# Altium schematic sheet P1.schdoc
size 609 x 533 mm; Symbol: Drawing-Symbol_A4; @Project Name: WYVERN-E; @Page Count: 1; @Update Date: 2026-08-05; @Create Date: 2026-08-05; @Schematic Name: Schematic1; @Page No: 1; @Page Name: P1; Company: EasyEDA.com; Version: V1.0; Page Size: A4; Device: Drawing-Symbol_A4; @Create Time: 14:42:15; @Update Time: 14:42:15; Border: 1; Width: 2400; Height: 2100; Region Start: 1; X Region Count: 6; Y Region Count: 4; Blade Width: 10; Title Block Position: 3; @Board Name: Board1
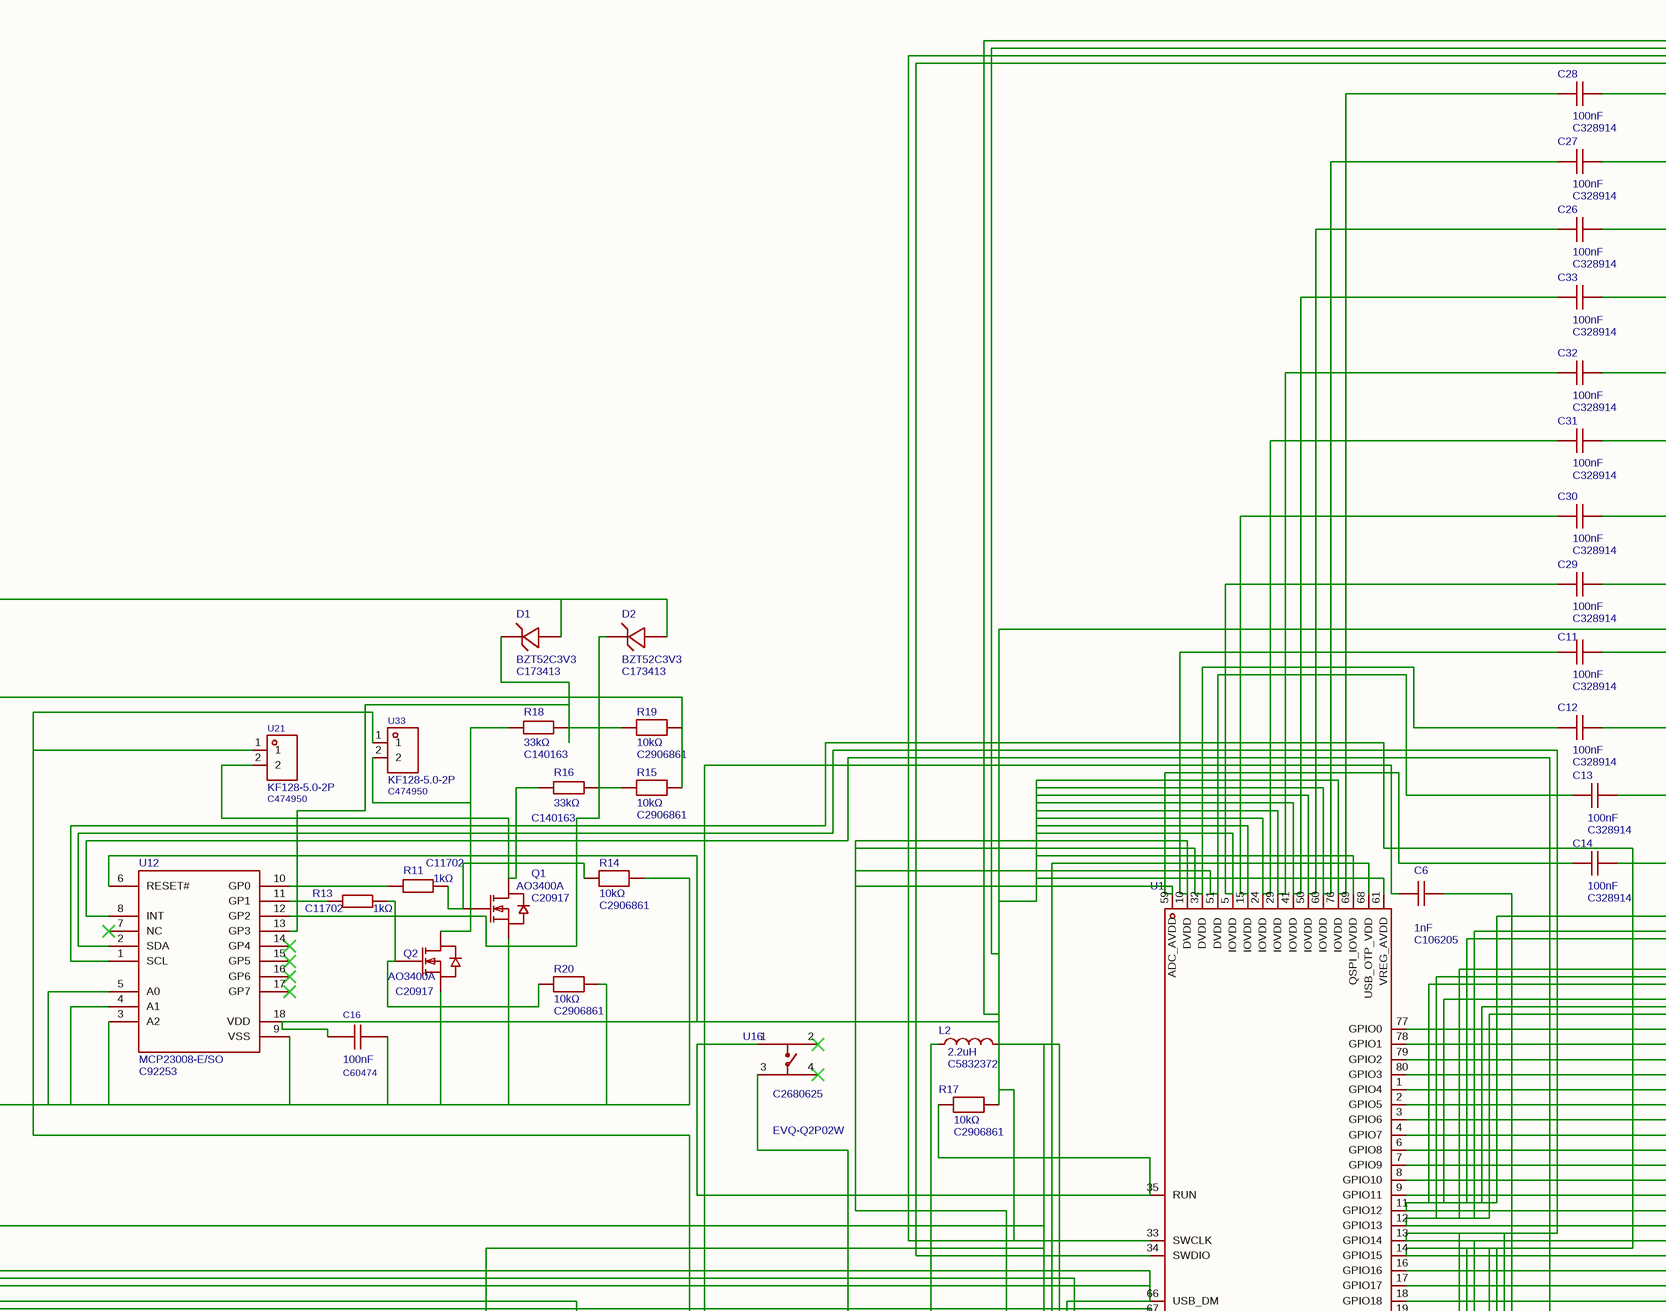
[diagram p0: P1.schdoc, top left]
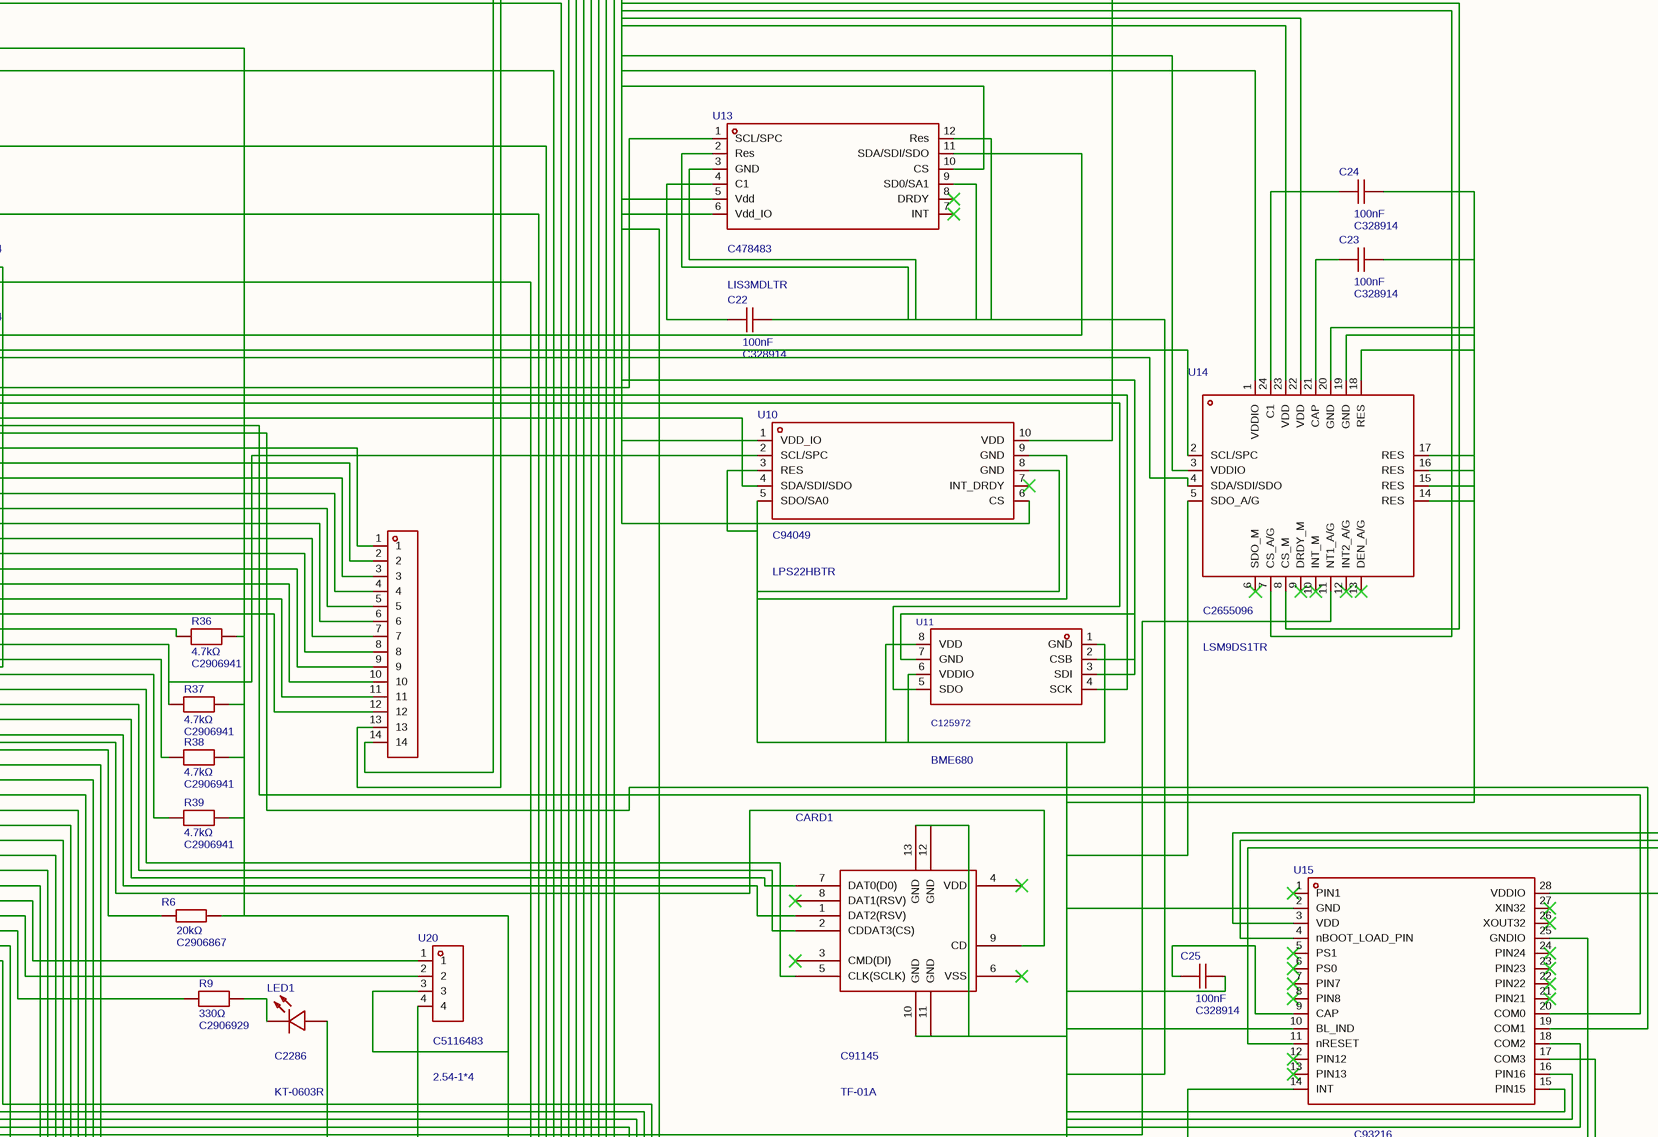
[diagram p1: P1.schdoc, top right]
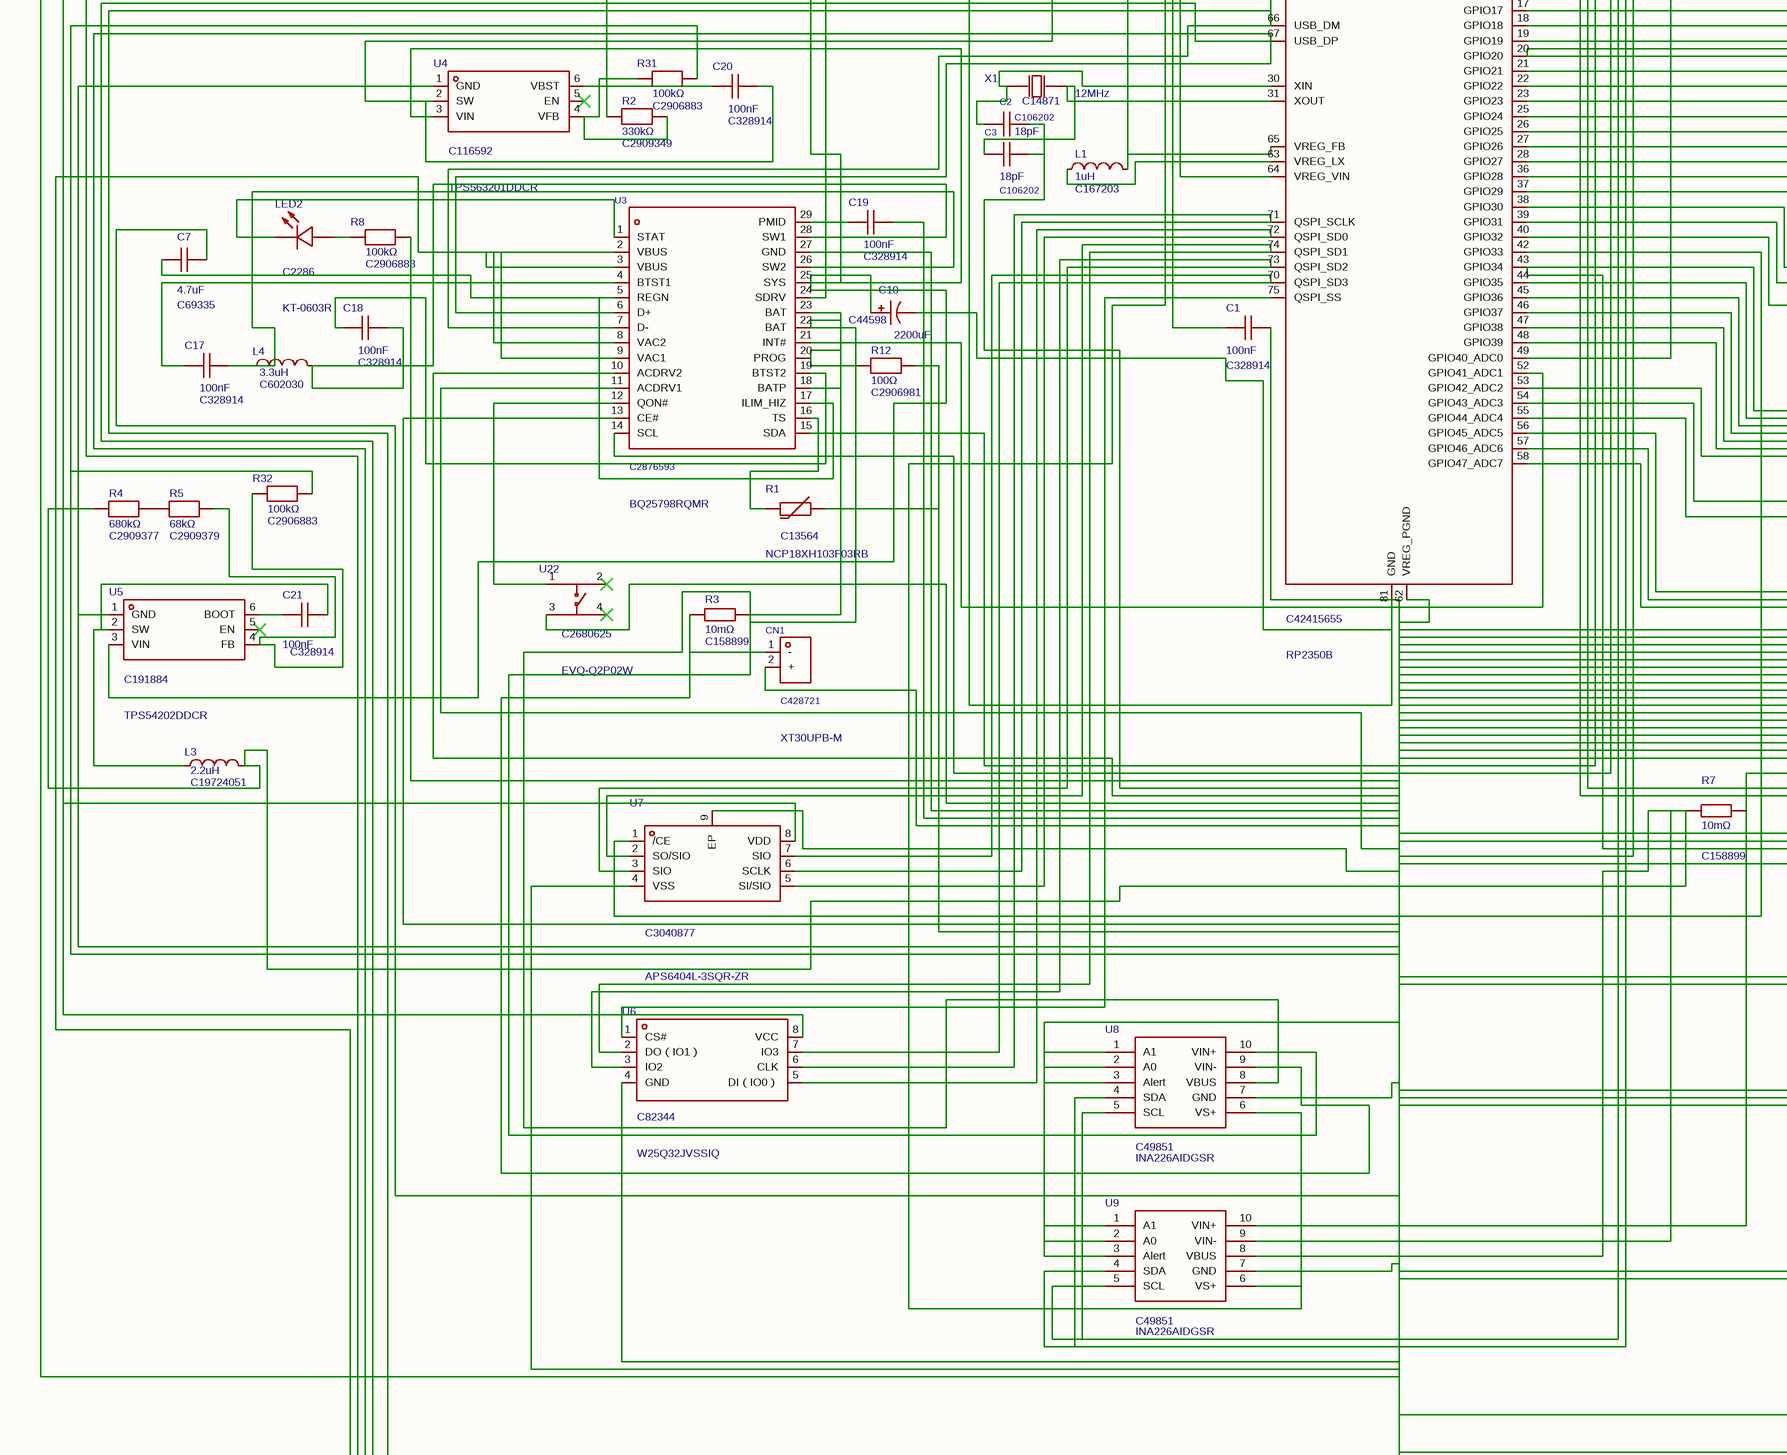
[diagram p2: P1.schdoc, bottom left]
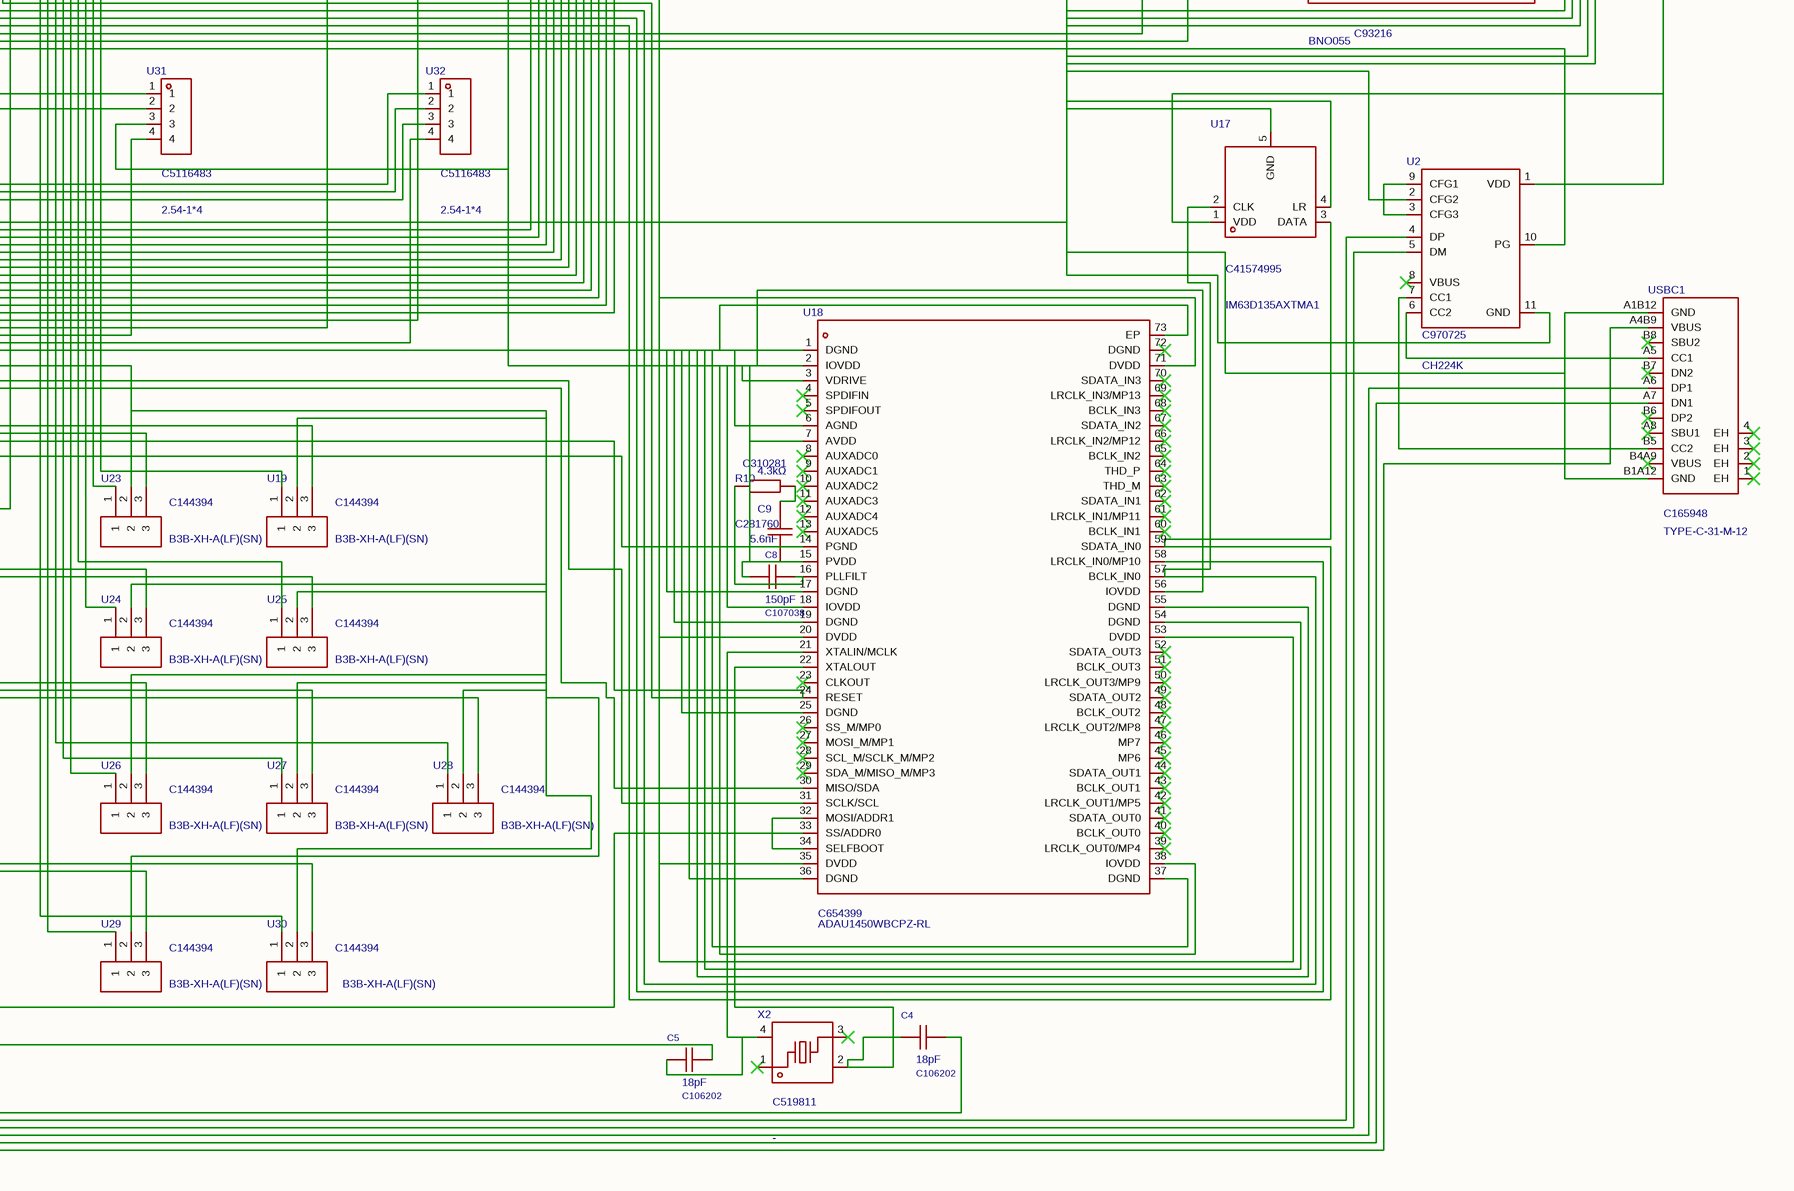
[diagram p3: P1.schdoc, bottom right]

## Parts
C1  100nF  Supplier Part: C328914  [C0402]
C2  18pF  Supplier Part: C106202  [C0402]
C3  18pF  Supplier Part: C106202  [C0402]
C4  18pF  Supplier Part: C106202  [C0402]
C5  18pF  Supplier Part: C106202  [C0402]
C6  1nF  Supplier Part: C106205  [C0402]
C7  4.7uF  Supplier Part: C69335  [C0603]
C8  150pF  Supplier Part: C107038  [C0603]
C9  5.6nF  Supplier Part: C281760  [C0402]
C10  2200uF  Supplier Part: C44598  [CAP-TH_BD13.0-P5.00-D1.2-FD]
C11  100nF  Supplier Part: C328914  [C0402]
C12  100nF  Supplier Part: C328914  [C0402]
C13  100nF  Supplier Part: C328914  [C0402]
C14  100nF  Supplier Part: C328914  [C0402]
C16  100nF  Supplier Part: C60474  [C0402]
C17  100nF  Supplier Part: C328914  [C0402]
C18  100nF  Supplier Part: C328914  [C0402]
C19  100nF  Supplier Part: C328914  [C0402]
C20  100nF  Supplier Part: C328914  [C0402]
C21  100nF  Supplier Part: C328914  [C0402]
C22  100nF  Supplier Part: C328914  [C0402]
C23  100nF  Supplier Part: C328914  [C0402]
C24  100nF  Supplier Part: C328914  [C0402]
C25  100nF  Supplier Part: C328914  [C0402]
C26  100nF  Supplier Part: C328914  [C0402]
C27  100nF  Supplier Part: C328914  [C0402]
C28  100nF  Supplier Part: C328914  [C0402]
C29  100nF  Supplier Part: C328914  [C0402]
C30  100nF  Supplier Part: C328914  [C0402]
C31  100nF  Supplier Part: C328914  [C0402]
C32  100nF  Supplier Part: C328914  [C0402]
C33  100nF  Supplier Part: C328914  [C0402]
CARD1  TF-01A  Supplier Part: C91145  [TF-SMD_TF-01A]
CN1  XT30UPB-M  Supplier Part: C428721  [CONN-TH_XT30UPB-M]
D1  BZT52C3V3  Supplier Part: C173413  [SOD-123_L2.7-W1.6-LS3.7-RD]
D2  BZT52C3V3  Supplier Part: C173413  [SOD-123_L2.7-W1.6-LS3.7-RD]
H1  2011-1X14G00SB  [HDR-TH_14P-P2.54-V-M_4]  (value not drawn)
L1  1uH  Supplier Part: C167203  [IND-SMD_L4.4-W4.2]
L2  2.2uH  Supplier Part: C5832372  [IND-SMD_L2.5-W2.0_MHCHL2520]
L3  2.2uH  Supplier Part: C19724051  [IND-SMD_L5.5-W5.2_NBMC0530N]
L4  3.3uH  Supplier Part: C602030  [IND-SMD_L4.0-W4.0]
LED1  KT-0603R  Supplier Part: C2286  [LED-SMD_L1.6-W0.8-R-RD]
LED2  KT-0603R  Supplier Part: C2286  [LED-SMD_L1.6-W0.8-R-RD]
Q1  AO3400A  Supplier Part: C20917  [SOT-23-3_L2.9-W1.3-P1.90-LS2.4-BR]
Q2  AO3400A  Supplier Part: C20917  [SOT-23-3_L2.9-W1.3-P1.90-LS2.4-BR]
R1  NCP18XH103F03RB  Supplier Part: C13564  [R0603]
R2  330kΩ  Supplier Part: C2909349  [R0402]
R3  10mΩ  Supplier Part: C158899  [R0603]
R4  680kΩ  Supplier Part: C2909377  [R0402]
R5  68kΩ  Supplier Part: C2909379  [R0402]
R6  20kΩ  Supplier Part: C2906867  [R0402]
R7  10mΩ  Supplier Part: C158899  [R0603]
R8  100kΩ  Supplier Part: C2906883  [R0402]
R9  330Ω  Supplier Part: C2906929  [R0402]
R10  4.3kΩ  Supplier Part: C310281  [R0603]
R11  1kΩ  Supplier Part: C11702  [R0402]
R12  100Ω  Supplier Part: C2906981  [R0603]
R13  1kΩ  Supplier Part: C11702  [R0402]
R14  10kΩ  Supplier Part: C2906861  [R0402]
R15  10kΩ  Supplier Part: C2906861  [R0402]
R16  33kΩ  Supplier Part: C140163  [R0402]
R17  10kΩ  Supplier Part: C2906861  [R0402]
R18  33kΩ  Supplier Part: C140163  [R0402]
R19  10kΩ  Supplier Part: C2906861  [R0402]
R20  10kΩ  Supplier Part: C2906861  [R0402]
R31  100kΩ  Supplier Part: C2906883  [R0402]
R32  100kΩ  Supplier Part: C2906883  [R0402]
R36  4.7kΩ  Supplier Part: C2906941  [R0402]
R37  4.7kΩ  Supplier Part: C2906941  [R0402]
R38  4.7kΩ  Supplier Part: C2906941  [R0402]
R39  4.7kΩ  Supplier Part: C2906941  [R0402]
U1  RP2350B  Supplier Part: C42415655  [QFN-80_L10.0-W10.0-P0.40-TL-EP3.4]
U2  CH224K  Supplier Part: C970725  [ESSOP-10_L4.9-W3.9-P1.0-LS6.0-TL-EP]
U3  BQ25798RQMR  Supplier Part: C2876593  [QFN-29_L4.0-W4.0-P0.40-TL-BQ25792RQMR]
U4  TPS563201DDCR  Supplier Part: C116592  [SOT-23-6_L2.9-W1.6-P0.95-LS2.8-BR]
U5  TPS54202DDCR  Supplier Part: C191884  [SOT-23-6_L2.9-W1.6-P0.95-LS2.8-BL]
U6  W25Q32JVSSIQ  Supplier Part: C82344  [SOIC-8_L5.3-W5.3-P1.27-LS8.0-BL]
U7  APS6404L-3SQR-ZR  Supplier Part: C3040877  [USON-8_L3.0-W2.0-P0.50-BL-EP]
U8  INA226AIDGSR  Supplier Part: C49851  [MSOP-10_L3.0-W3.0-P0.50-LS5.0-BL]
U9  INA226AIDGSR  Supplier Part: C49851  [MSOP-10_L3.0-W3.0-P0.50-LS5.0-BL]
U10  LPS22HBTR  Supplier Part: C94049  [HLGA-10L_LPS22HBTR]
U11  BME680  Supplier Part: C125972  [LGA-8_L3.0-W3.0-P0.80-TR]
U12  MCP23008-E/SO  Supplier Part: C92253  [SOIC-18_L11.6-W7.5-P1.27-LS10.3-BL]
U13  LIS3MDLTR  Supplier Part: C478483  [LGA-12_L2.0-W2.0-P0.50-BL]
U14  LSM9DS1TR  Supplier Part: C2655096  [LGA-24_L3.5-W3.0-P0.43-TL]
U15  BNO055  Supplier Part: C93216  [LGA-28_L5.2-W3.8-P0.50-BL]
U16  EVQ-Q2P02W  Supplier Part: C2680625  [SW-SMD_4P-L6.5-W6.0-P4.00-LS6.6-TL]
U17  IM63D135AXTMA1  Supplier Part: C41574995  [MIC-SMD_5P-L3.5-W2.7_IM66D130AXTMA1]
U18  ADAU1450WBCPZ-RL  Supplier Part: C654399  [LFCSP-72_L10.0-W9.8-P0.50-LS10.2-TL-EP5.5]
U19  B3B-XH-A(LF)(SN)  Supplier Part: C144394  [CONN-TH_3P-P2.50_A2501WV2-3P]
U20  2.54-1*4  Supplier Part: C5116483  [HDR-TH_4P-P2.54-V-M-1]
U21  KF128-5.0-2P  Supplier Part: C474950  [CONN-TH_P5.00_KF128-5.0-2P]
U22  EVQ-Q2P02W  Supplier Part: C2680625  [SW-SMD_4P-L6.5-W6.0-P4.00-LS6.6-TL]
U23  B3B-XH-A(LF)(SN)  Supplier Part: C144394  [CONN-TH_3P-P2.50_A2501WV2-3P]
U24  B3B-XH-A(LF)(SN)  Supplier Part: C144394  [CONN-TH_3P-P2.50_A2501WV2-3P]
U25  B3B-XH-A(LF)(SN)  Supplier Part: C144394  [CONN-TH_3P-P2.50_A2501WV2-3P]
U26  B3B-XH-A(LF)(SN)  Supplier Part: C144394  [CONN-TH_3P-P2.50_A2501WV2-3P]
U27  B3B-XH-A(LF)(SN)  Supplier Part: C144394  [CONN-TH_3P-P2.50_A2501WV2-3P]
U28  B3B-XH-A(LF)(SN)  Supplier Part: C144394  [CONN-TH_3P-P2.50_A2501WV2-3P]
U29  B3B-XH-A(LF)(SN)  Supplier Part: C144394  [CONN-TH_3P-P2.50_A2501WV2-3P]
U30  B3B-XH-A(LF)(SN)  Supplier Part: C144394  [CONN-TH_3P-P2.50_A2501WV2-3P]
U31  2.54-1*4  Supplier Part: C5116483  [HDR-TH_4P-P2.54-V-M-1]
U32  2.54-1*4  Supplier Part: C5116483  [HDR-TH_4P-P2.54-V-M-1]
U33  KF128-5.0-2P  Supplier Part: C474950  [CONN-TH_P5.00_KF128-5.0-2P]
USBC1  TYPE-C-31-M-12  Supplier Part: C165948  [USB-C_SMD-TYPE-C-31-M-12_1]
X1  12MHz  Supplier Part: C14871  [HC-49S_L11.4-W4.8]
X2  -  Supplier Part: C519811  [CRYSTAL-SMD_4P-L3.2-W2.5-BL]

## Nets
NetC1_1: C1.1 U1.68(USB_OTP_VDD)
NetC1_2: C1.2 C2.2 C3.2 C4.2 C5.2 C6.2 C7.2 C10.2 C11.2 C12.2 C13.2 C14.2 C16.2 C19.2 C22.2 C23.2 C24.2 C25.2 C26.2 C27.2 C28.2 C29.2 C30.2 C31.2 C32.2 C33.2 CARD1.10(GND) CARD1.11(GND) CARD1.12(GND) CARD1.13(GND) CN1.2(+) D1.2(A) D2.2(A) LED1.1(A) Q1.2(S) Q2.2(S) R1.2 R8.2 R12.2 R14.2 R15.2 R19.2 R20.2 R31.2 R32.2 U1.62(VREG_PGND) U1.81(GND) U2.2(CFG2) U2.3(CFG3) U2.9(CFG1) U2.11(GND) U3.10(ACDRV2) U3.11(ACDRV1) U3.13(CE#) U3.27(GND) U4.1(GND) U5.1(GND) U6.4(GND) U7.4(VSS) U7.9(EP) U8.1(A1) U8.2(A0) U8.3(Alert) U8.7(GND) U9.1(A1) U9.2(A0) U9.3(Alert) U9.7(GND) U10.3(RES) U10.5(SDO/SA0) U10.8(GND) U10.9(GND) U11.1(GND) U11.6(VDDIO) U11.8(VDD) U12.3(A2) U12.4(A1) U12.5(A0) U12.9(VSS) U13.2(Res) U13.3(GND) U13.9(SD0/SA1) U13.12(Res) U14.5(SDO_A/G) U14.14(RES) U14.15(RES) U14.16(RES) U14.17(RES) U14.18(RES) U14.19(GND) U14.20(GND) U15.2(GND) U15.10(BL_IND) U15.15(PIN15) U15.16(PIN16) U15.17(COM3) U15.18(COM2) U15.25(GNDIO) U16.3 U17.4(LR) U17.5(GND) U18.1(DGND) U18.6(AGND) U18.14(PGND) U18.17(DGND) U18.19(DGND) U18.25(DGND) U18.32(MOSI/ADDR1) U18.33(SS/ADDR0) U18.34(SELFBOOT) U18.36(DGND) U18.37(DGND) U18.54(DGND) U18.55(DGND) U18.73(EP) U19.3 U20.4 U22.3 U23.3 U24.3 U25.3 U26.3 U27.3 U28.3 U29.3 U30.3 U31.4 U32.4 USBC1.A1B12(GND) USBC1.B1A12(GND)
NetC2_1: C2.1 U1.30(XIN) X1.2(OSC2)
NetC3_1: C3.1 U1.31(XOUT) X1.1(OSC1)
NetC4_1: C4.1 U18.22(XTALOUT) X2.2(GND)
NetC5_1: C5.1 U18.21(XTALIN/MCLK) X2.4(GND)
NetC6_1: C6.1 U3.24(SDRV)
NetC7_1: C7.1 U3.5(REGN) U3.17(ILIM_HIZ)
NetC8_1: C8.1 C9.1 C16.1 C26.1 C27.1 C28.1 C29.1 C30.1 C31.1 C32.1 C33.1 H1.13 L2.2 R2.1 R6.2 R17.2 R36.2 R37.2 R38.2 R39.2 U1.5(IOVDD) U1.15(IOVDD) U1.24(IOVDD) U1.29(IOVDD) U1.33(SWCLK) U1.41(IOVDD) U1.50(IOVDD) U1.60(IOVDD) U1.61(VREG_AVDD) U1.64(VREG_VIN) U1.69(QSPI_IOVDD) U1.76(IOVDD) U2.1(VDD) U6.8(VCC) U7.8(VDD) U8.6(VS+) U9.6(VS+) U10.1(VDD_IO) U10.6(CS) U10.10(VDD) U11.2(CSB) U11.3(SDI) U11.7(GND) U12.6(RESET#) U12.18(VDD) U13.5(Vdd) U13.6(Vdd_IO) U13.10(CS) U14.1(VDDIO) U14.3(VDDIO) U14.7(CS_A/G) U14.8(CS_M) U14.22(VDD) U14.23(VDD) U15.3(VDD) U15.4(nBOOT_LOAD_PIN) U15.11(nRESET) U15.28(VDDIO) U17.1(VDD) U18.2(IOVDD) U18.3(VDRIVE) U18.7(AVDD) U18.15(PVDD) U18.18(IOVDD) U18.20(DVDD) U18.35(DVDD) U18.38(IOVDD) U18.53(DVDD) U18.56(IOVDD) U18.71(DVDD) U20.3 U31.3
NetC8_2: C8.2 R10.1 U18.16(PLLFILT)
NetC9_2: C9.2 R10.2
NetC10_1: C10.1 U3.25(SYS) U4.3(VIN) U5.3(VIN) U21.1 U33.1
NetC11_1: C11.1 C12.1 C13.1 C14.1 L1.2 U1.10(DVDD) U1.32(DVDD) U1.51(DVDD) U1.59(ADC_AVDD) U1.65(VREG_FB)
NetC17_1: C17.1 U3.4(BTST1)
NetC17_2: C17.2 L4.1 U3.26(SW2)
NetC18_1: C18.1 U3.19(BTST2)
NetC18_2: C18.2 L4.2 U3.28(SW1)
NetC19_1: C19.1 U3.29(PMID)
NetC20_1: C20.1 U4.6(VBST)
NetC20_2: C20.2 L2.1 U4.2(SW)
NetC21_1: C21.1 U5.6(BOOT)
NetC21_2: C21.2 L3.1 U5.2(SW)
NetC22_1: C22.1 U13.4(C1)
NetC23_1: C23.1 U14.21(CAP)
NetC24_1: C24.1 U14.24(C1)
NetC25_1: C25.1 U15.9(CAP)
NetCARD1_1: CARD1.1(DAT2(RSV)) U1.19(GPIO19)
NetCARD1_2: CARD1.2(CDDAT3(CS)) U1.17(GPIO17)
NetCARD1_5: CARD1.5(CLK(SCLK)) U1.16(GPIO16)
NetCARD1_7: CARD1.7(DAT0(D0)) U1.18(GPIO18)
NetCARD1_9: CARD1.9(CD) R6.1 U1.20(GPIO20)
NetCN1_1: CN1.1(-) R3.2 U8.9(VIN-)
NetD1_1: D1.1(K) R18.2 R19.1 U12.13(GP3)
NetD2_1: D2.1(K) R15.1 R16.2 U12.12(GP2)
NetH1_1: H1.1 U1.77(GPIO0)
NetH1_2: H1.2 U1.78(GPIO1)
NetH1_3: H1.3 U1.79(GPIO2)
NetH1_4: H1.4 U1.80(GPIO3)
NetH1_5: H1.5 U1.1(GPIO4)
NetH1_6: H1.6 U1.2(GPIO5)
NetH1_7: H1.7 U1.3(GPIO6)
NetH1_8: H1.8 U1.4(GPIO7)
NetH1_9: H1.9 U1.6(GPIO8)
NetH1_10: H1.10 U1.7(GPIO9)
NetH1_11: H1.11 U1.8(GPIO10)
NetH1_12: H1.12 U1.9(GPIO11)
NetH1_14: H1.14 U1.34(SWDIO)
NetL1_1: L1.1 U1.63(VREG_LX)
NetL3_2: L3.2 R4.1 R7.2 U9.8(VBUS) U9.9(VIN-)
NetLED1_2: LED1.2(K) R9.2
NetLED2_1: LED2.1(A) R8.1
NetLED2_2: LED2.2(K) U3.1(STAT)
NetQ1_1: Q1.1(G) R11.2 R14.1
NetQ1_3: Q1.3(D) R16.1 U21.2
NetQ2_1: Q2.1(G) R13.2 R20.1
NetQ2_3: Q2.3(D) R18.1 U33.2
NetR1_1: R1.1 U3.16(TS)
NetR2_2: R2.2 R31.1 U4.4(VFB)
NetR3_1: R3.1 R12.1 U3.18(BATP) U3.20(PROG) U3.22(BAT) U3.23(BAT) U8.8(VBUS) U8.10(VIN+)
NetR4_2: R4.2 R5.1
NetR5_2: R5.2 R32.1 U5.4(FB)
NetR7_1: R7.1 U9.10(VIN+) U19.2 U23.2 U24.2 U25.2 U26.2 U27.2 U28.2 U29.2 U30.2
NetR9_1: R9.1 U1.40(GPIO32)
NetR11_1: R11.1 U12.10(GP0)
NetR13_1: R13.1 U12.11(GP1)
NetR17_1: R17.1 U1.35(RUN) U16.1
NetR36_1: R36.1 U1.11(GPIO12) U10.4(SDA/SDI/SDO) U11.5(SDO) U13.11(SDA/SDI/SDO) U14.4(SDA/SDI/SDO) U15.20(COM0)
NetR37_1: R37.1 U1.12(GPIO13) U10.2(SCL/SPC) U11.4(SCK) U13.1(SCL/SPC) U14.2(SCL/SPC) U15.19(COM1)
NetR38_1: R38.1 U1.13(GPIO14) U3.15(SDA) U8.4(SDA) U9.4(SDA) U12.2(SDA) U18.30(MISO/SDA)
NetR39_1: R39.1 U1.14(GPIO15) U3.14(SCL) U8.5(SCL) U9.5(SCL) U12.1(SCL) U18.31(SCLK/SCL)
NetU1_21: U1.21(GPIO21) U19.1
NetU1_22: U1.22(GPIO22) U23.1
NetU1_23: U1.23(GPIO23) U24.1
NetU1_25: U1.25(GPIO24) U25.1
NetU1_26: U1.26(GPIO25) U26.1
NetU1_27: U1.27(GPIO26) U27.1
NetU1_28: U1.28(GPIO27) U28.1
NetU1_36: U1.36(GPIO28) U29.1
NetU1_37: U1.37(GPIO29) U30.1
NetU1_38: U1.38(GPIO30) U20.1
NetU1_39: U1.39(GPIO31) U20.2
NetU1_42: U1.42(GPIO33) U7.1(/CE)
NetU1_43: U1.43(GPIO34) U18.24(RESET)
NetU1_44: U1.44(GPIO35) U17.2(CLK) U18.57(BCLK_IN0)
NetU1_45: U1.45(GPIO36) U18.58(LRCLK_IN0/MP10)
NetU1_46: U1.46(GPIO37) U17.3(DATA) U18.59(SDATA_IN0)
NetU1_47: U1.47(GPIO38) U14.11(NT1_A/G)
NetU1_48: U1.48(GPIO39) U15.14(INT)
NetU1_49: U1.49(GPIO40_ADC0) U12.8(INT)
NetU1_52: U1.52(GPIO41_ADC1) U3.21(INT#)
NetU1_53: U1.53(GPIO42_ADC2) U2.10(PG)
NetU1_54: U1.54(GPIO43_ADC3) U31.1
NetU1_55: U1.55(GPIO44_ADC4) U31.2
NetU1_56: U1.56(GPIO45_ADC5) U32.1
NetU1_57: U1.57(GPIO46_ADC6) U32.2
NetU1_58: U1.58(GPIO47_ADC7) U32.3
NetU1_66: U1.66(USB_DM) U2.4(DP) U3.7(D-) USBC1.A7(DN1)
NetU1_67: U1.67(USB_DP) U2.5(DM) U3.6(D+) USBC1.A6(DP1)
NetU1_70: U1.70(QSPI_SD3) U6.7(IO3) U7.7(SIO)
NetU1_71: U1.71(QSPI_SCLK) U6.6(CLK) U7.6(SCLK)
NetU1_72: U1.72(QSPI_SD0) U6.5(DI（IO0）) U7.5(SI/SIO)
NetU1_73: U1.73(QSPI_SD2) U6.3(IO2) U7.3(SIO)
NetU1_74: U1.74(QSPI_SD1) U6.2(DO（IO1）) U7.2(SO/SIO)
NetU1_75: U1.75(QSPI_SS) U6.1(CS#)
NetU2_6: U2.6(CC2) USBC1.A5(CC1)
NetU2_7: U2.7(CC1) USBC1.B5(CC2)
NetU3_2: U3.2(VBUS) U3.3(VBUS) U3.8(VAC2) U3.9(VAC1) USBC1.A4B9(VBUS)
NetU3_12: U3.12(QON#) U22.1

Not connected (* = marked no-connect by the designer): CARD1 3(CMD(DI))* 4(VDD)* 6(VSS)* 8(DAT1(RSV))*; U2 8(VBUS)*; U4 5(EN)*; U5 5(EN)*; U10 7(INT_DRDY)*; U12 7(NC)* 14(GP4)* 15(GP5)* 16(GP6)* 17(GP7)*; U13 7(INT)* 8(DRDY)*; U14 6(SDO_M)* 9(DRDY_M)* 10(INT_M)* 12(INT2_A/G)* 13(DEN_A/G)*; U15 1(PIN1)* 5(PS1)* 6(PS0)* 7(PIN7)* 8(PIN8)* 12(PIN12)* 13(PIN13)* 21(PIN21)* 22(PIN22)* 23(PIN23)* 24(PIN24)* 26(XOUT32)* 27(XIN32)*; U16 2* 4*; U18 4(SPDIFIN)* 5(SPDIFOUT)* 8(AUXADC0)* 9(AUXADC1)* 10(AUXADC2)* 11(AUXADC3)* 12(AUXADC4)* 13(AUXADC5)* 23(CLKOUT)* 26(SS_M/MP0)* 27(MOSI_M/MP1)* 28(SCL_M/SCLK_M/MP2)* 29(SDA_M/MISO_M/MP3)* 39(LRCLK_OUT0/MP4)* 40(BCLK_OUT0)* 41(SDATA_OUT0)* 42(LRCLK_OUT1/MP5)* 43(BCLK_OUT1)* 44(SDATA_OUT1)* 45(MP6)* 46(MP7)* 47(LRCLK_OUT2/MP8)* 48(BCLK_OUT2)* 49(SDATA_OUT2)* 50(LRCLK_OUT3/MP9)* 51(BCLK_OUT3)* 52(SDATA_OUT3)* 60(BCLK_IN1)* 61(LRCLK_IN1/MP11)* 62(SDATA_IN1)* 63(THD_M)* 64(THD_P)* 65(BCLK_IN2)* 66(LRCLK_IN2/MP12)* 67(SDATA_IN2)* 68(BCLK_IN3)* 69(LRCLK_IN3/MP13)* 70(SDATA_IN3)* 72(DGND)*; U22 2* 4*; USBC1 1(EH)* 2(EH)* 3(EH)* 4(EH)* A8(SBU1)* B4A9(VBUS)* B6(DP2)* B7(DN2)* B8(SBU2)*; X2 1* 3*

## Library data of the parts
C1 C11-C14 C17-C33 = FN15X104K160PNG: Capacitance:100nF Tolerance:±10% Tolerance:±10% Voltage Rating:16V Temperature Coefficient:X7R; Manufacturer: PSA(信昌电陶); AddInBom: yes; ModelId: b7d13df3e9464d7a99d0651d1a5b4d570819f05c4eef4c71ace90d822a990e87; ModelName: C0402_L1.0-W0.5-H0.5; ModelTransform: 39.37,19.685,0,0,0,0,0,0,0; Tolerance: ±10%; Voltage Rating: 16V; Temperature Coefficient: X7R
C2-C5 = CC0402JRNPO9BN180: Capacitance:18pF Tolerance:±5% Tolerance:±5% Voltage Rating:50V Temperature Coefficient:NP0; Manufacturer: YAGEO(国巨); AddInBom: yes; ModelId: b7d13df3e9464d7a99d0651d1a5b4d570819f05c4eef4c71ace90d822a990e87; ModelName: C0402_L1.0-W0.5-H0.5; ModelTransform: 39.37,19.685,0,0,0,0,0,0,0; Tolerance: ±5%; Voltage Rating: 50V; Temperature Coefficient: NP0
C6 = CC0402KRX7R9BB102: Capacitance: Tolerance:±10% Tolerance:±10% Voltage Rated: Temperature Coefficient:; Manufacturer: YAGEO(国巨); AddInBom: yes; ModelId: b7d13df3e9464d7a99d0651d1a5b4d570819f05c4eef4c71ace90d822a990e87; ModelName: C0402_L1.0-W0.5-H0.5; ModelTransform: 39.37,19.685,0,0,0,0,0,0,0; Tolerance: ±10%
C7 = CL10A475KA8NQNC: Capacitance:4.7uF Tolerance:±10% Tolerance:±10% Voltage Rating:25V Temperature Coefficient:X5R; Manufacturer: SAMSUNG(三星); AddInBom: yes; ModelId: 624118aa3cc7497086c383c2d72e08520819f05c4eef4c71ace90d822a990e87; ModelName: C0603_L1.6-W0.8-H0.8; ModelTransform: 62.992,31.496,0,0,0,0,0,0,0; Tolerance: ±10%; Voltage Rating: 25V; Temperature Coefficient: X5R
C8 = CC0603JRNPO9BN151: Capacitance:150pF Tolerance:±5% Tolerance:±5% Voltage Rating:50V Temperature Coefficient:NP0; Manufacturer: YAGEO(国巨); AddInBom: yes; ModelId: 624118aa3cc7497086c383c2d72e08520819f05c4eef4c71ace90d822a990e87; ModelName: C0603_L1.6-W0.8-H0.8; ModelTransform: 62.992,31.496,0,0,0,0,0,0,0; Tolerance: ±5%; Voltage Rating: 50V; Temperature Coefficient: NP0
C9 = CC0402KRX7R9BB562: Capacitance:5.6nF Tolerance:±10% Tolerance:±10% Voltage Rating:50V Temperature Coefficient:X7R; Manufacturer: YAGEO(国巨); AddInBom: yes; ModelId: b7d13df3e9464d7a99d0651d1a5b4d570819f05c4eef4c71ace90d822a990e87; ModelName: C0402_L1.0-W0.5-H0.5; ModelTransform: 39.37,19.685,0,0,0,0,0,0,0; Tolerance: ±10%; Voltage Rating: 50V; Temperature Coefficient: X7R
C10 = KM228M025J20RR0VH2FP0: Capacitance:2200uF Tolerance:±20% Tolerance:±20% Voltage Rating:25V Ripple Current:- Equivalent Series Resistance(ESR):- Pin Spacing:5mm Diameter:13mm Height - Seated (Max):20mm Lifetime:2000hrs@105℃; Manufacturer: Chengx(承兴); Symbol: 2200uF 25V 13*20; AddInBom: yes; ModelId: 7c9983bf978a4fc5a02c9caad056438d0819f05c4eef4c71ace90d822a990e87; ModelTransform: 492.5187,492.025,0,0,0,0,0,0,-137.795; Tolerance: ±20%; Voltage Rating: 25V; Pin Spacing: 5mm
C16 = CC0402KRX7R7BB104: Capacitance:100nF Tolerance:±10% Tolerance:±10% Voltage Rating:16V Temperature Coefficient:X7R; Manufacturer: YAGEO(国巨); AddInBom: yes; ModelId: b7d13df3e9464d7a99d0651d1a5b4d570819f05c4eef4c71ace90d822a990e87; ModelName: C0402_L1.0-W0.5-H0.5; ModelTransform: 39.37,19.685,0,0,0,0,0,0,0; Tolerance: ±10%; Voltage Rating: 16V; Temperature Coefficient: X7R
CARD1 = TF-01A_C91145: Card Connection Mode:Push-Push Card Type:MicroSD Card (TF Card) Connector Type:Connector and Ejector Additional Card Detection Pins:- Supplementary Features:With Locating Pins Height Above Board:1.85mm Operating Temperature:- Operating Temperature:-; Manufacturer: 韩国韩荣; Add into BOM: yes; ModelId: 5685a23adc9a4e3e9b914abe5ae03aae0819f05c4eef4c71ace90d822a990e87; ModelTransform: 633.85696,590.65303,0,0,0,0,0,-85.63,-23.622
CN1 = XT30UPB-M: Rated current:15A Rated voltage: colour:Yellow Connector type:Model aircraft plug contact resistance: interface form:Male insulating material: metal material:Gold plating; Manufacturer: AMASS(艾迈斯); Add into BOM: yes; ModelId: 8606296c6a2a4a0aa30f28b26a2c1e3a0819f05c4eef4c71ace90d822a990e87; ModelTransform: 401.574,204.724,0,0,0,0,0,0,-78.74; Rated current: 15A; interface form: Male
D1 D2 = BZT52C3V3_C173413: Diode Configuration:1 Independent Zener Voltage(Nom):3.3V Reverse Leakage Current (Ir):20uA@1V Zener Voltage(Range):3.14V~3.47V Zener Voltage(Range):3.14V~3.47V Pd - Power Dissipation:500mW Impedance(Zzt):130Ω Impedance(Zzk):- Operating Junction Temperatu; Manufacturer: MDD(辰达半导体); AddInBom: yes; ModelId: 31ae3d5c025440ebafdeabfabec0ebeb0819f05c4eef4c71ace90d822a990e87; ModelName: SOD-123_L2.7-W1.6-H1.4-LS3.7; ModelTransform: 146.026,62.992,0,180,0,0,0.0005,0,0; Zener Voltage(Nom): 3.3V; Pd - Power Dissipation: 500mW; Impedance(Zzt): 130Ω; Tolerance: ±5%
H1 = 2011-1X14G00SB: Pin Structure:1x14P Pitch:2.54mm Circluar Pins/Square Pins:Pin Header Mounting Type:Through Hole Number of Rows:1 Number of Pins:14P Current Rating:3A Voltage Rating (Max):600V Length of Mating Pin:6mm Insulation Height:2.5mm Length of End Connection Pin:; Manufacturer: WingTAT(格林柏); AddInBom: yes; ModelId: f6b8b1151f3d4858b245f95bf957bfbf0819f05c4eef4c71ace90d822a990e87; ModelTransform: 1399.997,98.8187,0,0,0,0,0,0,-118.11; Pin Structure: 1x14P; Pitch: 2.54mm; Current Rating: 3A; Voltage Rating (Max): 600V
L1 = FXL0420-1R0-M: Inductance:1uH Tolerance:±20% Tolerance:±20% Current Rating:6A Current - Saturation(Isat):7A DC Resistance(DCR):27mΩ Type:Molded Inductor; Manufacturer: cjiang(长江微电); AddInBom: yes; ModelId: 202f222253c645ab9b4a671ae12ae5590819f05c4eef4c71ace90d822a990e87; ModelName: IND-SMD_L4.2-W4.4-H2.0; ModelTransform: 173.228,165.354,0,0,0,0,0,0,0; Tolerance: ±20%; Current Rating: 6A; Current - Saturation(Isat): 7A; DC Resistance(DCR): 27mΩ
L2 = FTC252012S2R2MBCA: Inductance:2.2uH Tolerance:±20% Tolerance:±20% Current Rating:3A Current - Saturation(Isat):3.8A DC Resistance(DCR):55mΩ Type:-; Manufacturer: cjiang(长江微电); AddInBom: yes; ModelId: 6030ee72033e42b3943c7a42b03bf5750819f05c4eef4c71ace90d822a990e87; ModelTransform: 98.425,78.74,0,0,0,0,0,0,0; Tolerance: ±20%; Current Rating: 3A; Current - Saturation(Isat): 3.8A; DC Resistance(DCR): 55mΩ
L3 = CY0530AT125DS-2R2MCY: Inductance:2.2uH Tolerance:±20% Tolerance:±20% Current Rating:6A Current - Saturation(Isat):6.7A DC Resistance(DCR):17.3mΩ Type:- Ratings:-; Manufacturer: Sumida(胜美达); AddInBom: yes; Tolerance: ±20%; Current Rating: 6A; Current - Saturation(Isat): 6.7A; DC Resistance(DCR): 17.3mΩ
L4 = FHD4020S-3R3MT: Inductance:3.3uH Tolerance:±20% Tolerance:±20% Current Rating:4A Current - Saturation(Isat):5.9A DC Resistance(DCR):73mΩ Type:Winding Inductor; Manufacturer: cjiang(长江微电); AddInBom: yes; ModelId: eb765a5a931c40af9a8ef05b08821f350819f05c4eef4c71ace90d822a990e87; ModelName: IND-SMD_L4.0-W4.0-H1.9; ModelTransform: 157.48,157.484,0,0,0,0,0,0,0; Tolerance: ±20%; Current Rating: 4A; Current - Saturation(Isat): 5.9A; DC Resistance(DCR): 73mΩ
LED1 LED2 = KT-0603R: Lamp Holder Type:1.6mm x 0.8mm square LED Illumination Color:Red Voltage - Forward(Vf):1.8V~2.4V Voltage - Forward(Vf):1.8V~2.4V Power(Watts):40mW Forward Current:20mA Wavelength - Dominant:615nm~630nm Wavelength - Dominant:615nm~630nm Peak Wavelength:645; Manufacturer: KENTO; Add into BOM: yes; ModelId: 19cc79473bbc420a8203ad67d1a57d420819f05c4eef4c71ace90d822a990e87; ModelName: LED0603_L1.6-W0.8-H0.6; ModelTransform: 63.7794,31.496,0,0,0,0,0,0,0; Illumination Color: Red; Power(Watts): 40mW; Forward Current: 20mA; Peak Wavelength: 645nm; Diode Configuration: Discrete Diode; Lens Color: Water Clear; Luminous Intensity: 300mcd; Viewing Angle: 120°
Q1 Q2 = AO3400A_C20917: Number:- Drain to Source Voltage:30V Current - Continuous Drain(Id):- RDS(on):48mΩ@2.5V Pd - Power Dissipation:- Gate Threshold Voltage (Vgs(th)):1.45V@250uA Gate Charge(Qg):7nC@10V Input Capacitance(Ciss):630pF@15V Reverse Transfer Capacitance (Crss@Vds); Manufacturer: AOS; AddInBom: yes; ModelId: 62a57c6760504a01965db6419a6d07df0819f05c4eef4c71ace90d822a990e87; ModelName: SOT-23-3P_L2.9-W1.3-H1.0-LS2.4-P0.95; ModelTransform: 98.425,114.173,0,180,0,0,0.0005,-0.0005,0; Drain to Source Voltage: 30V; Type: N-Channel
R1 = NCP18XH103F03RB: Power(Watts):100mW Resistance @ 25℃:10kΩ Resistance Tolerance:±1% Resistance Tolerance:±1% B Constant Tolerance:±1% B Constant (25℃/50℃):3380K B Constant (25℃/75℃):- B Constant (25℃/85℃):3434K B Constant (25℃/100℃):3455K Steady State Current (Max):310uA D; Manufacturer: muRata(村田); Add into BOM: yes; ModelId: 112863783b5b41f1b5254f87eedc79320819f05c4eef4c71ace90d822a990e87; ModelTransform: 31.8897,63.7794,0,90,0,0,0,0,0; Power(Watts): 100mW; Resistance @ 25℃: 10kΩ; Resistance Tolerance: ±1%; B Constant (25℃/50℃): 3380K; B Constant (25℃/85℃): 3434K; B Constant (25℃/100℃): 3455K; Steady State Current (Max): 310uA; Dissipation Factor: 1mW/℃
R2 = FRC0402F3303TS: Type:Thick Film Resistor Resistance:330kΩ Tolerance:±1% Tolerance:±1% Power(Watts):62.5mW Voltage-Supply(Max):50V Temperature Coefficient:±100ppm/℃ Temperature Coefficient:±100ppm/℃ Operating Temperature:-55℃~+155℃ Operating Temperature:-55℃~+155℃; Manufacturer: FOJAN(富捷); AddInBom: yes; ModelId: efdecb7dae4442949d28eecaf748420f0819f05c4eef4c71ace90d822a990e87; ModelName: R0402_L1.0-W0.5-H0.4; ModelTransform: 39.37,19.685,0,0,0,0,0,0,0; Tolerance: ±1%; Power(Watts): 62.5mW; Voltage-Supply(Max): 50V
R3 R7 = RTT03R010FTP: Type:Thick Film Resistor Resistance:10mΩ Tolerance:±1% Tolerance:±1% Power(Watts):100mW Temperature Coefficient:±1500ppm/℃ Temperature Coefficient:±1500ppm/℃ Operating Temperature:-55℃~+155℃ Operating Temperature:-55℃~+155℃; Manufacturer: RALEC(旺诠); 3D Model: 112863783b5b41f1b5254f87eedc79320819f05c4eef4c71ace90d822a990e87; 3D Model Transform: 31.8897,63.7794,0,90,0,0,0,0,0; Tolerance: ±1%; Power(Watts): 100mW; AddInBom: yes
R4 = FRC0402F6803TS: Type:Thick Film Resistor Resistance:680kΩ Tolerance:±1% Tolerance:±1% Power(Watts):62.5mW Voltage-Supply(Max):50V Temperature Coefficient:±100ppm/℃ Temperature Coefficient:±100ppm/℃ Operating Temperature:-55℃~+155℃ Operating Temperature:-55℃~+155℃; Manufacturer: FOJAN(富捷); AddInBom: yes; ModelId: efdecb7dae4442949d28eecaf748420f0819f05c4eef4c71ace90d822a990e87; ModelName: R0402_L1.0-W0.5-H0.4; ModelTransform: 39.37,19.685,0,0,0,0,0,0,0; Tolerance: ±1%; Power(Watts): 62.5mW; Voltage-Supply(Max): 50V
R5 = FRC0402F6802TS: Type:Thick Film Resistor Resistance:68kΩ Tolerance:±1% Tolerance:±1% Power(Watts):62.5mW Voltage-Supply(Max):50V Temperature Coefficient:±100ppm/℃ Temperature Coefficient:±100ppm/℃ Operating Temperature:-55℃~+155℃ Operating Temperature:-55℃~+155℃; Manufacturer: FOJAN(富捷); AddInBom: yes; ModelId: efdecb7dae4442949d28eecaf748420f0819f05c4eef4c71ace90d822a990e87; ModelName: R0402_L1.0-W0.5-H0.4; ModelTransform: 39.37,19.685,0,0,0,0,0,0,0; Tolerance: ±1%; Power(Watts): 62.5mW; Voltage-Supply(Max): 50V
R6 = FRC0402F2002TS: Type:Thick Film Resistor Resistance:20kΩ Tolerance:±1% Tolerance:±1% Power(Watts):62.5mW Voltage-Supply(Max):50V Temperature Coefficient:±100ppm/℃ Temperature Coefficient:±100ppm/℃ Operating Temperature:-55℃~+155℃ Operating Temperature:-55℃~+155℃; Manufacturer: FOJAN(富捷); AddInBom: yes; ModelId: efdecb7dae4442949d28eecaf748420f0819f05c4eef4c71ace90d822a990e87; ModelName: R0402_L1.0-W0.5-H0.4; ModelTransform: 39.37,19.685,0,0,0,0,0,0,0; Tolerance: ±1%; Power(Watts): 62.5mW; Voltage-Supply(Max): 50V
R8 R31 R32 = FRC0402J104 TS: Type:Thick Film Resistor Resistance:100kΩ Tolerance:±5% Tolerance:±5% Power(Watts):62.5mW Voltage-Supply(Max):50V Temperature Coefficient:±100ppm/℃ Temperature Coefficient:±100ppm/℃ Operating Temperature:-55℃~+155℃ Operating Temperature:-55℃~+155℃; Manufacturer: FOJAN(富捷); AddInBom: yes; ModelId: efdecb7dae4442949d28eecaf748420f0819f05c4eef4c71ace90d822a990e87; ModelName: R0402_L1.0-W0.5-H0.4; ModelTransform: 39.37,19.685,0,0,0,0,0,0,0; Tolerance: ±5%; Power(Watts): 62.5mW; Voltage-Supply(Max): 50V
R9 = FRC0402J331 TS: Type:Thick Film Resistor Resistance:330Ω Tolerance:±5% Tolerance:±5% Power(Watts):62.5mW Voltage-Supply(Max):50V Temperature Coefficient:±100ppm/℃ Temperature Coefficient:±100ppm/℃ Operating Temperature:-55℃~+155℃ Operating Temperature:-55℃~+155℃; Manufacturer: FOJAN(富捷); AddInBom: yes; ModelId: efdecb7dae4442949d28eecaf748420f0819f05c4eef4c71ace90d822a990e87; ModelName: R0402_L1.0-W0.5-H0.4; ModelTransform: 39.37,19.685,0,0,0,0,0,0,0; Tolerance: ±5%; Power(Watts): 62.5mW; Voltage-Supply(Max): 50V
R10 = RS-03K4301FT: Type:Thick Film Resistors Resistance:4.3kΩ Tolerance:±1% Tolerance:±1% Power(Watts): Overload Voltage (Max): Temperature Coefficient:±100ppm/℃ Temperature Coefficient:±100ppm/℃ Operating Temperature Range:-55℃~+155℃ Operating Temperature Range:-55℃~+155℃; Manufacturer: FH(风华); AddInBom: yes; ModelId: 112863783b5b41f1b5254f87eedc79320819f05c4eef4c71ace90d822a990e87; ModelTransform: 31.8897,63.7794,0,90,0,0,0,0,0; Tolerance: ±1%
R11 R13 = 0402WGF1001TCE: Type:Thick Film Resistor Resistance:1kΩ Tolerance:±1% Tolerance:±1% Power(Watts):62.5mW Voltage-Supply(Max):50V Temperature Coefficient:±100ppm/℃ Temperature Coefficient:±100ppm/℃ Operating Temperature:-55℃~+155℃ Operating Temperature:-55℃~+155℃; Manufacturer: UNI-ROYAL(厚声); AddInBom: yes; ModelId: efdecb7dae4442949d28eecaf748420f0819f05c4eef4c71ace90d822a990e87; ModelName: R0402_L1.0-W0.5-H0.4; ModelTransform: 39.37,19.685,0,0,0,0,0,0,0; Tolerance: ±1%; Power(Watts): 62.5mW; Voltage-Supply(Max): 50V
R12 = FRC0603F1000TS: Type:Thick Film Resistor Resistance:100Ω Tolerance:±1% Tolerance:±1% Power(Watts):100mW Voltage-Supply(Max):75V Temperature Coefficient:±100ppm/℃ Temperature Coefficient:±100ppm/℃ Operating Temperature:-55℃~+155℃ Operating Temperature:-55℃~+155℃; Manufacturer: FOJAN(富捷); AddInBom: yes; ModelId: 112863783b5b41f1b5254f87eedc79320819f05c4eef4c71ace90d822a990e87; ModelTransform: 31.8897,63.7794,0,90,0,0,0,0,0; Tolerance: ±1%; Power(Watts): 100mW; Voltage-Supply(Max): 75V
R14 R15 R19 R20 = FRC0402F1002TS: Type:Thick Film Resistor Resistance:10kΩ Tolerance:±1% Tolerance:±1% Power(Watts):62.5mW Voltage-Supply(Max):50V Temperature Coefficient:±100ppm/℃ Temperature Coefficient:±100ppm/℃ Operating Temperature:-55℃~+155℃ Operating Temperature:-55℃~+155℃; Manufacturer: FOJAN(富捷); 3D Model: efdecb7dae4442949d28eecaf748420f0819f05c4eef4c71ace90d822a990e87; 3D Model Transform: 39.37,19.685,0,0,0,0,0,0,0; Tolerance: ±1%; Power(Watts): 62.5mW; Voltage-Supply(Max): 50V; AddInBom: yes; ModelName: R0402_L1.0-W0.5-H0.4
R16 R18 = RC-02K3302FT: Type:Thick Film Resistor Resistance:33kΩ Tolerance:±1% Tolerance:±1% Power(Watts):62.5mW Voltage-Supply(Max):50V Temperature Coefficient:±100ppm/℃ Temperature Coefficient:±100ppm/℃ Operating Temperature:-55℃~+155℃ Operating Temperature:-55℃~+155℃; Manufacturer: FH(风华); AddInBom: yes; ModelId: efdecb7dae4442949d28eecaf748420f0819f05c4eef4c71ace90d822a990e87; ModelName: R0402_L1.0-W0.5-H0.4; ModelTransform: 39.37,19.685,0,0,0,0,0,0,0; Tolerance: ±1%; Power(Watts): 62.5mW; Voltage-Supply(Max): 50V
R17 = FRC0402F1002TS: Type:Thick Film Resistor Resistance:10kΩ Tolerance:±1% Tolerance:±1% Power(Watts):62.5mW Voltage-Supply(Max):50V Temperature Coefficient:±100ppm/℃ Temperature Coefficient:±100ppm/℃ Operating Temperature:-55℃~+155℃ Operating Temperature:-55℃~+155℃; Manufacturer: FOJAN(富捷); AddInBom: yes; ModelId: efdecb7dae4442949d28eecaf748420f0819f05c4eef4c71ace90d822a990e87; ModelName: R0402_L1.0-W0.5-H0.4; ModelTransform: 39.37,19.685,0,0,0,0,0,0,0; Tolerance: ±1%; Power(Watts): 62.5mW; Voltage-Supply(Max): 50V
R36-R39 = FRC0402J472 TS: Type:Thick Film Resistor Resistance:4.7kΩ Tolerance:±5% Tolerance:±5% Power(Watts):62.5mW Voltage-Supply(Max):50V Temperature Coefficient:±100ppm/℃ Temperature Coefficient:±100ppm/℃ Operating Temperature:-55℃~+155℃ Operating Temperature:-55℃~+155℃; Manufacturer: FOJAN(富捷); AddInBom: yes; ModelId: efdecb7dae4442949d28eecaf748420f0819f05c4eef4c71ace90d822a990e87; ModelName: R0402_L1.0-W0.5-H0.4; ModelTransform: 39.37,19.685,0,0,0,0,0,0,0; Tolerance: ±5%; Power(Watts): 62.5mW; Voltage-Supply(Max): 50V
U1 = RP2350B_C42415655: Number of I/O:48 Features:Independent watchdog (IWDG)；Power-on reset (POR)；True random number generator (TRNG)；Watchdog reset；Built-in general-purpose timer；Hardware ECC check；External pin reset (NRST)；Integrated LDO; Manufacturer: Raspberry Pi(树莓派); Add into BOM: yes; ModelId: 9f007f8a42644ad5aa4c6524189812eb0819f05c4eef4c71ace90d822a990e87; ModelTransform: 394.487,394.487,0,0,0,0,0,0,0; Number of I/O: 48
U2 = CH224K: Type:Power Receiver Controller Protocol:PD 3.0 Number of Channels:- Output Power:100W Output Voltage:5V；20V；15V；12V；9V Voltage - Supply:4V~30V Voltage - Supply:4V~30V Operating Temperature:-40℃~+90℃ Operating Temperature:-40℃~+90℃ Features:Thermal Protect; Manufacturer: WCH(南京沁恒); Add into BOM: yes; ModelId: caddd54494d446ce85a816aa480d5ff10819f05c4eef4c71ace90d822a990e87; ModelTransform: 192.913,236.22,0,0,0,0,0,0,0; Protocol: PD 3.0; Output Power: 100W; Voltage - Supply: 4V~30V
U3 = BQ25798RQMR: The Chip Type:Charging IC Voltage - Supply:3.6V~24V Voltage - Supply:3.6V~24V Charge Current - Max:5A Type of Battery:Lithium Battery Number of Cells:1~4 Number of Cells:1~4 Operating Temperature:-40℃~+85℃ Operating Temperature:-40℃~+85℃ Battery Temperatu; Manufacturer: TI(德州仪器); Add into BOM: yes; ModelId: 359ccb1411cf4750b283dd43433afa970819f05c4eef4c71ace90d822a990e87; ModelTransform: 158.267,158.267,0,0,0,0,0,-0.197,0; Charge Current - Max: 5A; Number of Cells: 1~4; Battery Temperature Detection: Support; Supply Current (Iq): 17uA; Interface: I2C
U4 = TPS563201DDCR: Function:Step-down type Voltage - Supply:4.5V~17V Voltage - Supply:4.5V~17V Output Voltage:768mV~7V Output Voltage:768mV~7V Output Current:3A Frequency - Switching:580kHz Frequency - Switching:580kHz Operating Temperature:-40℃~+125℃@(TJ) Operating Tempera; Manufacturer: TI(德州仪器); Add into BOM: yes; ModelId: 1370be37a17e44418ae52e2b4cc1f5e50819f05c4eef4c71ace90d822a990e87; ModelName: SOT-23-6_L2.9-W1.6-H1.5-LS2.8-P0.95; ModelTransform: 110.73671,114.173,0,180,0,0,0.001,-0.003,0; Output Current: 3A; Frequency - Switching: 580kHz; Number of Outputs: 1; Topology: Buck; Quiescent Current: 380uA; Switch tube (built-in/external): Built-in; Output Type: Adjustable
U5 = TPS54202DDCR: Function:Step-down type Voltage - Supply:4.5V~28V Voltage - Supply:4.5V~28V Output Voltage:- Output Voltage:- Output Current:2A Frequency - Switching:500kHz Frequency - Switching:500kHz Operating Temperature:-40℃~+125℃@(TJ) Operating Temperature:-40℃~+125; Manufacturer: TI(德州仪器); Add into BOM: yes; ModelId: 1370be37a17e44418ae52e2b4cc1f5e50819f05c4eef4c71ace90d822a990e87; ModelName: SOT-23-6_L2.9-W1.6-H1.5-LS2.8-P0.95; ModelTransform: 110.236,113.364,0,90,0,0,0.0005,0.0005,0; Output Current: 2A; Frequency - Switching: 500kHz; Number of Outputs: 1; Topology: Buck; Quiescent Current: 45uA; Switch tube (built-in/external): Built-in; Output Type: Adjustable
U6 = W25Q32JVSSIQ_C82344: Interface:SPI Memory Size:32Mbit Clock Frequency:133MHz Voltage - Supply:2.7V~3.6V Voltage - Supply:2.7V~3.6V Standby Supply Current:10uA Program / Erase Cycles:100,000 cycles Write Cycle Time (tWC):- Page Programming Time (Tpp):3ms Block Erase Time(tBE):; Manufacturer: Winbond(华邦); Add into BOM: yes; ModelId: 7b3104f4a302484e875593c5ba7bd3db0819f05c4eef4c71ace90d822a990e87; ModelName: SOIC-8_L5.3-W5.3-H1.9-LS7.9-P1.27; ModelTransform: 208.661,311.25654,0,0,0,0,-0.0005,0.0005,0; Interface: SPI; Memory Size: 32Mbit; Clock Frequency: 133MHz; Standby Supply Current: 10uA; Page Programming Time (Tpp): 3ms; Block Erase Time(tBE): 120ms@(32KB); Data Retention - TDR (Year): 20 Years
U7 = APS6404L-3SQR-ZR: Manufacturer: Apmemory; Add into BOM: yes; ModelId: 2b35e1c3dcc44b77887d4f445b51370a0819f05c4eef4c71ace90d822a990e87; ModelName: USON-8_L2-W3-H0.6X0.5P; ModelTransform: 79.527,118.8974,0,0,0,0,-0.313,-1.1,0
U8 U9 = INA226AIDGSR: Number of Channels:- Vcm - Common Mode Voltage:0V~36V Vcm - Common Mode Voltage:0V~36V Gain:- Bandwidth:- Ib - Input Bias Current:100pA Vos - Input Offset Voltage:2.5uV Operating Temperature:-40℃~+125℃ Operating Temperature:-40℃~+125℃ Differential Voltage; Manufacturer: TI(德州仪器); Add into BOM: yes; ModelId: 875cf331c88d40d1aea94374997f39b10819f05c4eef4c71ace90d822a990e87; ModelName: MSOP-10_L3.0-W3.0-H1.1-LS5.0-P0.50; ModelTransform: 118.11,196.85,0,0,0,0,0,0,0; Vcm - Common Mode Voltage: 0V~36V; Ib - Input Bias Current: 100pA; Vos - Input Offset Voltage: 2.5uV; Differential Voltage: ±40V; Single Supply: 2.7V~5.5V; Quiescent Current: 330uA; Input Offset Voltage Drift(Vos TC): 0.1uV/℃; Common Mode Rejection Ratio (CMRR): 140dB
U10 = LPS22HBTR: Pressure range:26Kpa~1.26bar Pressure range:26Kpa~1.26bar Voltage - Supply:1.7V~3.6V Voltage - Supply:1.7V~3.6V Standby Current:1uA Interface:SPI；I2C Module:No Absolute Accuracy:0.1hpa Relative Accuracy:0.1hpa Features:On-chip temperature compensation；Int; Manufacturer: ST(意法半导体); Add into BOM: yes; ModelId: 02ad9adc3b5149f0a499482c2afb62890819f05c4eef4c71ace90d822a990e87; ModelName: HLGA-10L_L2.0-W2.0-H0.8-P0.5-LPS22HBTR; ModelTransform: 78.74,78.74,0,0,0,0,0,0.195,0; Standby Current: 1uA; Module: No; Absolute Accuracy: 0.1hpa
U11 = BME680: Pressure range:30Kpa~1.1bar Pressure range:30Kpa~1.1bar Voltage - Supply:1.71V~3.6V Voltage - Supply:1.71V~3.6V Standby Current:150nA Interface:SPI；I2C Module:- Absolute Accuracy:0.6hpa Relative Accuracy:0.12hpa Features:Standby mode；Integrated ADC and di; Manufacturer: Bosch(博世); Add into BOM: yes; ModelId: b8c5a93640fd43cf889b444887718f200819f05c4eef4c71ace90d822a990e87; ModelName: LGA-8_L3.0-W3.0-H0.9-P0.80-TR; ModelTransform: 118.11,118.11,0,0,0,0,0,0,0; Standby Current: 150nA; Absolute Accuracy: 0.6hpa; Temperature Coefficient of Offset(TCO): 1.3pa/K
U12 = MCP23008-E/SO: Interface:I2C Number of I/O:8 Interrupt Output:With Interrupt Output Output Type:- Voltage - Supply:1.8V~5.5V Voltage - Supply:1.8V~5.5V Current - Output Low(IOL):- Current - Output High(IOH):- Clock Frequency:1.7MHz Operating Temperature:-40℃~+125℃ Opera; Manufacturer: MICROCHIP(美国微芯); AddInBom: yes; ModelId: 9c95af80582940178ddf2179f3334e830819f05c4eef4c71ace90d822a990e87; ModelName: SOIC-18_L11.6-W7.5-H2.7-LS10.3-P1.27; ModelTransform: 456.692,409.68154,0,0,0,0,0,0,0; Interface: I2C; Number of I/O: 8; Clock Frequency: 1.7MHz
U13 = LIS3MDLTR: Magnetic Sensing Range(X,Y):±1.2mT；±1.6mT；±4Gs；±8Gs Magnetic Sensing Range(X,Y):±1.2mT；±1.6mT；±4Gs；±8Gs Magnetic Sensing Range(Z):±4Gs；±1.2mT；±8Gs；±1.6mT Magnetic Sensing Range(Z):±4Gs；±1.2mT；±8Gs；±1.6mT Output bit:16bit Interface Type:SPI；I2C Voltage - S; Manufacturer: ST(意法半导体); Add into BOM: yes; ModelId: 08d0e00f89c34818888f739e33f114130819f05c4eef4c71ace90d822a990e87; ModelName: LGA-12_L2.0-W2.0-H1.0-P0.50; ModelTransform: 78.74,78.74,0,90,0,0,0,0.001,0; Output bit: 16bit; Voltage - Supply: 1.9V~3.6V; Current - Supply: 270uA；1uA；40uA
U14 = LSM9DS1TR: Accelerometer Sensing Axis:X,Y,Z Acceleration Measurement Range (MAX):±16g Acceleration Measurement Range (MAX):±16g Gyroscope Sensing Axis:X,Y,Z Gyroscope Measurement Range (MAX):±2000dps Gyroscope Measurement Range (MAX):±2000dps Sensor Type:IMU (accele; Manufacturer: ST(意法半导体); Add into BOM: yes; ModelId: 06729e712fbf436e90dfd5c95b7315ee0819f05c4eef4c71ace90d822a990e87; ModelTransform: 137.795,118.11,0,0,0,0,0,0,0; Accelerometer Sensing Axis: X,Y,Z; Acceleration Measurement Range (MAX): ±16g; Sensor Type: IMU (accelerometer + gyroscope); Output Bits: 16bit; Interface: I2C；SPI; Voltage - Supply: 1.9V~3.6V
U15 = BNO055: Accelerometer Sensing Axis:X,Y,Z Acceleration Measurement Range (MAX):±16g Acceleration Measurement Range (MAX):±16g Gyroscope Sensing Axis:X,Y,Z Gyroscope Measurement Range (MAX):±2000dps Gyroscope Measurement Range (MAX):±2000dps Sensor Type:IMU (accele; Manufacturer: Bosch(博世); Add into BOM: yes; ModelId: 2256a7a8c01e4b8c876389a77bde68f70819f05c4eef4c71ace90d822a990e87; ModelName: LGA-28_L5.2-W3.8-H1.2-P0.50-BL; ModelTransform: 204.724,149.606,0,90,0,0,-0.004,0.004,0; Accelerometer Sensing Axis: X,Y,Z; Acceleration Measurement Range (MAX): ±16g; Sensor Type: IMU (accelerometer + gyroscope); Output Bits: 14bit；16bit; Interface: UART；I2C; Voltage - Supply: 2.4V~3.6V; Standby Current: 40uA
U16 U22 = EVQ-Q2P02W: Circuit:SPST Actuator Style:Round Button Operating Force:1.6N Mounting Type:Surface Mount,Vertical Length:6.5mm Width:6mm Switch Height:2.5mm Contact Current:20mA Voltage Rating:15V With Lamp:- IP Rating:- Termination Style:J-Lead Life:1,000,000 cycles Op; Manufacturer: PANASONIC(松下); Add into BOM: yes; ModelId: fe986412e056403e95cd55841a82b76e0819f05c4eef4c71ace90d822a990e87; ModelTransform: 260.751,240.337,0,0,0,0,-0.001,0,0; Circuit: SPST; Operating Force: 1.6N; Switch Height: 2.5mm; Contact Current: 20mA; Voltage Rating: 15V
U17 = IM63D135AXTMA1: Direction:Omnidirectional Voltage - Supply:1.8V Voltage - Supply:1.8V Current Consumption:1.1mA~1.4mA Current Consumption:1.1mA~1.4mA S/N Ratio:63.5dB Sensitivity:-41dB Sensitivity:-41dB Length:3.5mm Width:2.65mm Height:0.98mm Operating Temperature:-40℃~+; Manufacturer: Infineon(英飞凌); Add into BOM: yes; ModelId: d3258170ac2d45d5985ecf8dc254410c0819f05c4eef4c71ace90d822a990e87; ModelTransform: 104.3305,137.795,0,0,0,0,0,2.402,0; Voltage - Supply: 1.8V; S/N Ratio: 63.5dB; Sensitivity: -41dB
U18 = ADAU1450WBCPZ-RL: Operating Temperature Range:-40℃~+105℃ Operating Temperature Range:-40℃~+105℃; Manufacturer: ADI(亚德诺); Add into BOM: yes; ModelId: e0591baa79fb4cafa64304a2951a30980819f05c4eef4c71ace90d822a990e87; ModelName: LFCSP-72_L10.0-W9.8-H1.0-P0.50; ModelTransform: 394.487,386.6134,0,0,0,0,-0.591,0.392,0
U19 U23-U30 = B3B-XH-A(LF)(SN): Pins Structure:1x3P Pitch:2.5mm Mounting Type:Through Hole Reference Series:XH Number of Pins:3P Number of Rows:1 Number of PINs Per Row:3 Row Spacing:- Current Rating:3A Contact Material:Brass Contact Plating:Tin Operating Temperature:-25℃~+85℃ Operating; Manufacturer: JST; Add into BOM: yes; ModelId: 5bef03a823d44d6d8bbe2419212192340819f05c4eef4c71ace90d822a990e87; ModelTransform: 393.7,226.3775,0,0,0,0,-0.005,-18.465,-125.984; Pins Structure: 1x3P; Pitch: 2.5mm; Reference Series: XH; Number of PINs Per Row: 3; Current Rating: 3A; Voltage Rating: 250V; Plastic Material: PA66; Flame Retardant Rating: UL94V-0; Supplementary Features: K Pin; Z-Height of the Board: 7mm; X-Length of Bottom Edge on Board (Spacing Line): 9.9mm; Y-Width of Bottom Edge on Board: 5.75mm
U20 U31 U32 = 2.54-1*4: Pin Structure:1x4P Pitch:2.54mm Circluar Pins/Square Pins:Pin Header Mounting Type:Through Hole Number of Rows:1 Number of Pins:4P Current Rating:2.5A Length of Mating Pin:6mm Insulation Height:2.54mm Length of End Connection Pin:3mm Contact Material:Bras; Manufacturer: ZHOURI(洲日); Add into BOM: yes; ModelId: e2e03939c192453cba872779c0cb63900819f05c4eef4c71ace90d822a990e87; ModelTransform: 400.039,100,0,0,0,0,0,0,-118.11; Pin Structure: 1x4P; Pitch: 2.54mm; Current Rating: 2.5A
U21 U33 = KF128-5.0-2P: Number of Positions or Pins:1x2P Pitch:5mm Color:Green Mounting Type:Through Hole Number of Pins:2P Number of Rows:1 Number of PINs Per Row:2 Current Rating:24A Voltage Rating (Max):250V Wire Gauge - AWG:12~22 Wire Gauge - mm2:2.5 Wire Gauge - mm2:2.5 Ope; Manufacturer: KEFA(科发); AddInBom: yes; ModelId: f8352b58be624e57aa604c4a1e8e24950819f05c4eef4c71ace90d822a990e87; ModelTransform: 405.511,417.322,0,0,0,0,-5.906,0,-169.291; Number of Positions or Pins: 1x2P; Pitch: 5mm; Number of PINs Per Row: 2; Current Rating: 24A; Voltage Rating (Max): 250V; Wire Gauge - AWG: 12~22; Wire Gauge - mm2: 2.5
USBC1 = TYPE-C-31-M-12: Connector Type:Type-C Protocol Standard:- Gender:Female Mounting Type:Surface Mount, Right Angle Number of Contacts:16P Number of Ports:1 Current Rating-Power:5A Voltage Rating:20V Connect-Disconnect Life:10,000 cycles Length:7.35mm Operating Temperature:; Manufacturer: 韩国韩荣; Add into BOM: yes; ModelId: 8421221a464047838322348b3a9debc30819f05c4eef4c71ace90d822a990e87; ModelTransform: 351.9678,311.023,0,180,0,0,0,-43.307,-33.465; Connector Type: Type-C; Gender: Female; Number of Contacts: 16P; Number of Ports: 1; Current Rating-Power: 5A; Voltage Rating: 20V
X1 = X49SM12MSD2SC: Type:Crystal Oscillator Frequency:12MHz Normal temperature Frequency Tolerance:±20ppm Normal temperature Frequency Tolerance:±20ppm Load Capacitance:20pF Frequency Stability:±30ppm Frequency Stability:±30ppm Operating Temperature:-20℃~+70℃ Operating Tempe; Manufacturer: YXC(扬兴晶振); Add into BOM: yes; ModelId: c2ec6472aa1a474698dd1da780b3c79b0819f05c4eef4c71ace90d822a990e87; ModelName: HC-49S_L11.4-W1.8-H3.0-LS12.7; ModelTransform: 499.999,188.976,0,0,0,0,0,0,0; Normal temperature Frequency Tolerance: ±20ppm; Load Capacitance: 20pF; Frequency Stability: ±30ppm
X2 = NX3225GA-12.288MHz-STD-CRG-2: Type:- Frequency:- Load Capacitance:- Operating Temperature:- Operating Temperature:-; Manufacturer: NDK; Add into BOM: yes; ModelId: a2b47bc5d32f4dfd996128e047b549a00819f05c4eef4c71ace90d822a990e87; ModelTransform: 125.984,98.425,0,0,0,0,0,0,0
